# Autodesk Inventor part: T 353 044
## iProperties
Company: Mayer & Müller AG Schaltgeräte
Created: 2006-06
Part Number: T 353 044
Material: 2.0596.01
Document SubType Name: Modeling
Designer: I.Baliuc
Description: Buchse
Density: 8.2 g/cm^3
Author: T.Messerschmitt
Revision Number: 353044
Keywords: aus 353006
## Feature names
1. Extrusion2
2. Extrusion3
3. Bohrung_Ø6 [Hole]
